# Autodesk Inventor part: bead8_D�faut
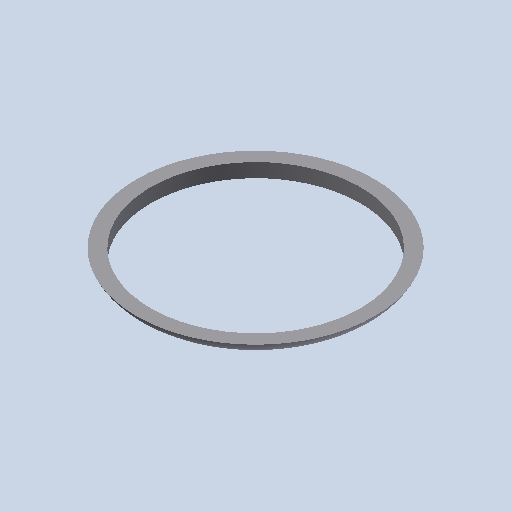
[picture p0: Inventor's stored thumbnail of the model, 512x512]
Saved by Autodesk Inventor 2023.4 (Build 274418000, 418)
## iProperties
Created: 2011-01
Part Number: bead8_D�faut
Document SubType Name: Modeling
Designer: eric
Density: 1 g/cm^3
Mass: 0.24495 g
Surface Area: 6.79212 cm^2
Volume: 0.24495 cm^3
Material: Générique
Appearance: Par défaut
Author: eric
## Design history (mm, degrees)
feature "Base1"
node "Corps solides"
node "Corps surfaciques"
node "Solide1"
